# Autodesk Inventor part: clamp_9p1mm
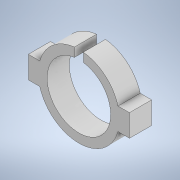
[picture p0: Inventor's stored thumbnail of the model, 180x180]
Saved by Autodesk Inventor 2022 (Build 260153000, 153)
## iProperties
Created: 2022-12
Part Number: clamp_9p1mm
Material: Generic
Document SubType Name: Modeling
Designer: suerfu
Density: 1 g/cm^3
Appearance: Default
Author: suerfu
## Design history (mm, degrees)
sketch "Sketch1"
  geometry: L1 (-5.599, 1.588)-(-7.239, 1.588); L2 (-7.239, 1.588)-(-7.239, -1.587); L3 (-7.239, -1.587)-(-5.599, -1.587); L4 (-5.599, -1.587)-(-5.599, 1.588); L5 (5.599, 1.588)-(7.239, 1.588); L6 (7.239, 1.588)-(7.239, -1.587); L7 (7.239, -1.587)-(5.599, -1.587); L8 (5.599, -1.587)-(5.599, 1.588); L9 (-0.635, 5.785)-(0.635, 5.785); L10 (0.635, 5.785)-(0.635, 4.505); L11 (0.635, 4.505)-(-0.635, 4.505); L12 (-0.635, 4.505)-(-0.635, 5.785); A1 r 4.55 centre (0, 0) between (-0.635, 4.505) and (0.635, 4.505); A2 r 5.82 centre (0, 0) between (-0.635, 5.785) and (0.635, 5.785); 3 further points
  constraints: 24 end point, 10 point on circle, 6 parallel, 3 horizontal, 3 perpendicular, 2 centre point, 2 coincident, 1 collinear, 1 point on line
  dimensions: "d0" = 9.1 diameter of A1; "d1" = 11.64 diameter of A2 (computed from d0); "d2" = 3.175 distance of L1.end L2.end; "d5" = 1.27 distance of L9.start L9.end; "d8" = 14.478 distance between parallel lines of L6 L2
extrude "Extrusion1" new body sketch "Sketch1" distance "d6" = 3.175; taper "d7" = 0 deg
body "Solid1"
